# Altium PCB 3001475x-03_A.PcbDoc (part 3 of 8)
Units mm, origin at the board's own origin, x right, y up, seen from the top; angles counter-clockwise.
Board outline 100 x 72 mm, 12 copper layers (Top Layer, L2 GND, Layer 3, L4 GND, Layer 5, L6 PWR, L7 3V3, Layer 8, L9 GND, Layer 10, L11 GND, Bottom Layer), stack 1.735 mm thick; 428 components, 499 nets, 1973 pads, 1473 vias.
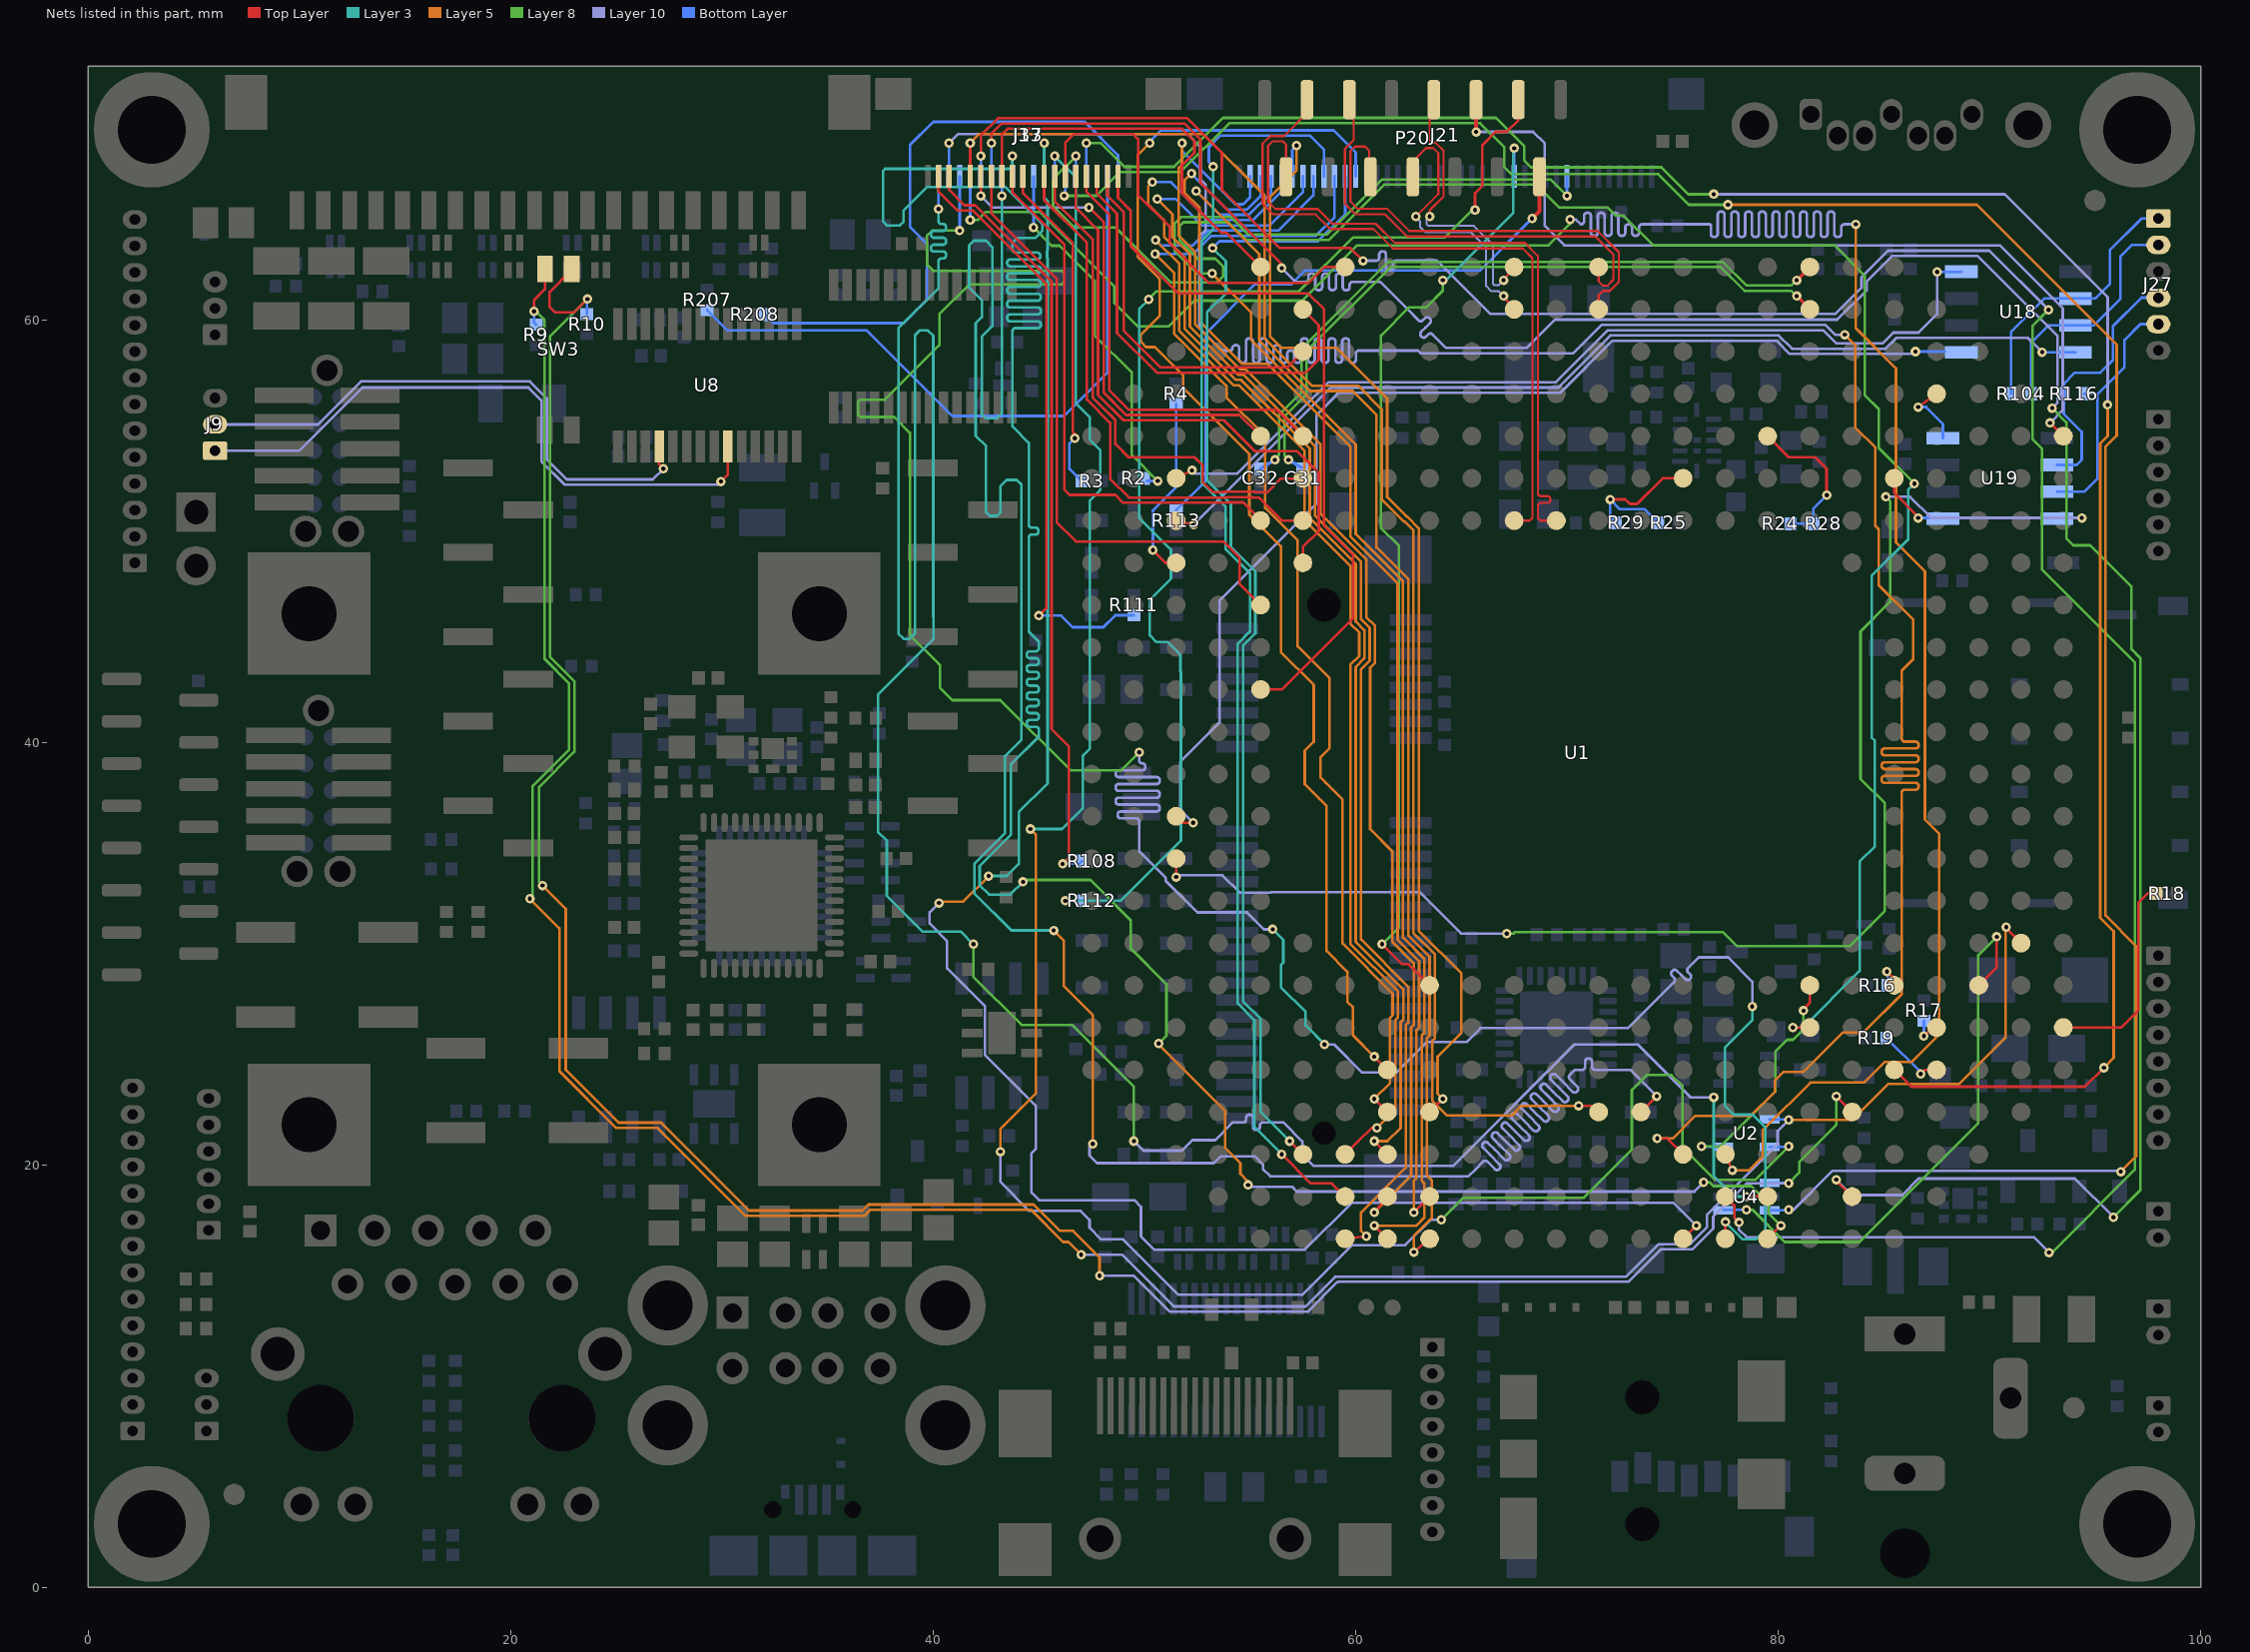
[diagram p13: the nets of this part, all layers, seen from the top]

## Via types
v1: diameter 0.45, hole 0.2, Top Layer to Bottom Layer, 1473 vias

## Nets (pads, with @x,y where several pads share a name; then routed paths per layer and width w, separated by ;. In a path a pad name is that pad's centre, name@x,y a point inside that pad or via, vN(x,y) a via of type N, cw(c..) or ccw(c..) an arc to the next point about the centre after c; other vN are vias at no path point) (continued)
BOOT_CFG_1_4: R18.1 U1.W24 | length 10
  Top Layer w0.125: U1.W24@93.5,26.5 96.25,26.5 97.05,27.3 97.05,32.4 97.5,32.85 R18.1@97.92,32.85
BOOT_CFG_1_5: R10.1 SW3.3 U1.AA19 U4.1 | length 117.3
  Top Layer w0.125: SW3.3@22.884,62.367 21.837,61.321 21.837,60.613 22.1,60.35 22.986,60.35 v1(23.625,60.988) ; SW3.3@22.885,62.367 SW3.3@22.885,62.41 ; v1(82.75,23.25) U1.AA19@83.5,22.5
  Layer 8 w0.125: v1(21.5,33.225) 21.337,33.388 21.337,37.884 23.013,39.559 23.013,42.891 21.85,44.054 21.85,58.854 21.85,59.214 v1(23.625,60.988) ; v1(80.5,19.125) 81,19.625 81,20.137 82.75,21.887 v1(82.75,23.25)
  Layer 5 w0.125: v1(21.5,33.225) 22.6,32.125 22.6,24.5 25.1,22 27.125,22 31.288,17.837 36.638,17.837 36.925,18.125 44.75,18.125 46,16.875 46.625,16.875 47.875,15.625 v1(47.875,14.75)
  Layer 10 w0.125: v1(47.875,14.75) 49.5,14.75 51.2,13.05 57.736,13.05 59.136,14.45 59.167,14.45 59.179,14.463 72.913,14.463 74.45,16 75.937,16 76.925,16.988 76.925,17.55 78.5,19.125 v1(80.5,19.125)
  Bottom Layer w0.125: R10.1@23.6,60.28 23.6,60.964 v1(23.625,60.988) ; U4.1@79.6,19.15 v1@80.475,19.15
BOOT_CFG_1_6: R9.1 SW3.4 U1.U23 U2.1 | length 127.4
  Top Layer w0.125: v1(21.1,60.4) 21.1,60.937 21.615,61.452 SW3.4@21.615,62.41 ; v1(90.8,31.25) 90.8,31.2 U1.U23@91.5,30.5
  Layer 8 w0.125: v1(20.9,32.6) 21.038,32.738 21.038,37.938 22.763,39.663 22.763,42.787 21.6,43.95 21.6,60 21.2,60.4 v1(21.1,60.4)
  Layer 5 w0.125: v1(20.9,32.6) 22.3,31.2 22.3,24.446 24.996,21.75 26.95,21.75 31.113,17.587 36.741,17.587 37.029,17.875 44.625,17.875 46.15,16.35 46.4,16.35 v1(47,15.75) ; v1(80.5,22.125) 83.5,22.125 85.212,23.837 88.571,23.837 90.763,26.029 90.763,31.213 v1(90.8,31.25)
  Layer 10 w0.125: v1(47,15.75) 48.946,15.75 51.396,13.3 57.632,13.3 59.032,14.7 59.063,14.7 59.076,14.713 72.809,14.713 74.346,16.25 75.833,16.25 76.625,17.042 76.625,17.625 79.975,20.975 79.975,21.608 80.492,22.125 v1(80.5,22.125)
  Bottom Layer w0.125: v1(21.1,60.4) 21.1,59.88 R9.1@21.2,59.78 ; U2.1@79.6,22.15 v1@80.475,22.15
BOOT_CFG_1_7: R19.1 U1.Y21 | length 3.2
  Top Layer w0.125: v1(86.75,24.3) 86.95,24.5 U1.Y21@87.5,24.5
  Bottom Layer w0.125: R19.1@85.13,26 86.75,24.38 v1(86.75,24.3)
BOOT_CFG_2_5: R16.1 U1.V20 | length 1.5
  Top Layer w0.125: v1(85.15,29.15) 85.5,28.8 U1.V20@85.5,28.5
  Bottom Layer w0.125: v1(85.15,29.15) 85.18,29.12 R16.1@85.18,28.5
BOOT_CFG_2_6: R17.1 U1.W21 | length 1.5
  Top Layer w0.125: v1(86.9,26.1) 87.3,26.5 U1.W21@87.5,26.5
  Bottom Layer w0.125: v1(86.9,26.1) R17.1@86.9,26.82
BOOT_MODE0: R24.1 R28.1 U1.E17 | length 7.7
  Top Layer w0.125: U1.E17@79.5,54.5 80.5,53.5 81.75,53.5 82.294,52.956 82.294,51.556 82.3,51.562 v1(82.3,51.7)
  Bottom Layer w0.125: R24.1@80.58,50.35 81.52,50.35 R28.1@81.67,50.5 ; R28.1@81.67,50.35 R28.1@81.67,50.5 ; v1(82.3,51.7) 81.67,51.07 R28.1@81.67,50.5
BOOT_MODE1: R25.1 R29.1 U1.F15 | length 8
  Top Layer w0.125: v1(72.05,51.5) 72.767,51.5 72.979,51.287 73.321,51.287 74.533,52.5 U1.F15@75.5,52.5
  Bottom Layer w0.125: R29.1@72.32,50.4 72.05,50.67 v1(72.05,51.5) 72.512,51.038 73.682,51.038 R25.1@74.32,50.4
BT_DISABLE_N: R4.2 U1.H3 | length 8.7
  Top Layer w0.125: v1(50.4,49.1) 51,48.5 U1.H3@51.5,48.5
  Bottom Layer w0.125: v1(50.4,49.1) 50.4,50.975 51.5,52.075 R4.2@51.5,56.02
CAN1_H: J27.2 R104.2 U18.7 | length 11.5
  Bottom Layer w0.125: R104.2@91.98,56.5 91.98,58.93 92.79,59.74 U18.7@94.075,59.74 94.95,59.74 96.2,60.99 96.2,63 96.75,63.55 J27.2@98,63.55
CAN1_L: J27.1 R104.1 U18.6 | length 13.1
  Bottom Layer w0.125: R104.1@91.02,56.5 91.02,59.42 92.61,61.01 U18.6@94.075,61.01 95.01,61.01 95.7,61.7 95.7,63.3 97.2,64.8 J27.1@98,64.8
CAN1_RXD: U1.F3 U18.4 | length 43
  Top Layer w0.125: U1.F3@51.5,52.5 v1(52.25,52.875)
  Layer 10 w0.125: v1(52.25,52.875) 52.413,52.712 54.384,52.712 58.721,57.05 69.483,57.05 71.946,59.513 82.137,59.513 82.763,58.887 84.937,58.887 85.45,59.4 86.65,59.4 87.525,60.275 v1(87.525,62.275)
  Bottom Layer w0.125: v1(87.525,62.275) 88.67,62.275 U18.4@88.675,62.28
CAN1_STBY: U1.G3 U18.8 | length 47.1
  Top Layer w0.125: U1.G3@51.5,50.5 v1(52.325,50.3)
  Layer 10 w0.125: v1(52.325,50.3) 58.825,56.8 69.587,56.8 72.049,59.263 80.029,59.263 80.654,58.637 85.087,58.637 85.6,59.15 91.825,59.15 v1(92.5,58.475)
  Bottom Layer w0.125: v1@92.5,58.47 U18.8@94.075,58.47
CAN1_TXD: U1.P3 U18.1 | length 54.7
  Top Layer w0.125: U1.P3@51.5,36.5 51.8,36.2 v1(52.3,36.2)
  Layer 10 w0.125: v1(52.3,36.2) 51.687,36.813 51.687,39.074 53.55,40.937 53.55,46.712 58.15,51.312 58.15,55.5 59.2,56.55 69.69,56.55 72.153,59.013 79.925,59.013 80.55,58.387 86.387,58.387 v1(86.5,58.5)
  Bottom Layer w0.125: v1(86.5,58.5) 87.895,58.5
CAN2_H: J27.5 R116.2 U19.7 | length 11.8
  Bottom Layer w0.125: U19.7@93.2,51.865 94.49,51.865 95.125,52.5 95.125,56.5 ; R116.2@94.48,56.5 95.125,56.5 ; J27.5@98,59.8 97.15,59.8 96.4,59.05 96.4,57.775 95.125,56.5
CAN2_L: J27.4 R116.1 U19.6 | length 12.3
  Bottom Layer w0.125: U19.6@93.2,53.135 94.135,53.135 94.375,53.375 94.375,54.7 93.52,55.555 R116.1@93.52,56.5 93.52,56.97 94.05,57.5 95.25,57.5 95.85,58.1 95.85,59.7 97.2,61.05 J27.4@98,61.05
CAN2_RXD: U1.D21 U19.4 | length 3.3
  Top Layer w0.125: v1(86.625,55.875) U1.D21@87.5,56.5
  Bottom Layer w0.125: v1(86.625,55.875) 87,55.875 87.8,55.075 U19.4@87.8,54.405
CAN2_STBY: U1.R3 U19.8 | length 68.2
  Top Layer w0.125: v1(51.5,33.625) U1.R3@51.5,34.5
  Layer 8 w0.125: v1(67.15,30.95) 67.467,30.95 67.529,31.013 77.387,31.013 78.05,30.35 83.375,30.35 85.05,32.025 85.05,37.125 83.9,38.275 83.9,45.25 85.3,46.65 85.3,51.425 v1(85.1,51.625)
  Layer 10 w0.125: v1(51.5,33.625) 51.588,33.713 53.687,33.713 54.513,32.887 55.971,32.887 55.996,32.913 63.021,32.913 64.983,30.95 v1(67.15,30.95) ; v1(85.1,51.625) 86.25,51.625 87.25,50.625 v1(94.375,50.625)
  Bottom Layer w0.125: U19.8@93.23,50.625 v1(94.375,50.625)
CAN2_TXD: U1.F20 U19.1 | length 3.5
  Top Layer w0.125: U1.F20@85.5,52.5 85.5,51.808 86.625,50.683 v1(86.625,50.625)
  Bottom Layer w0.125: v1(86.625,50.625) U19.1@87.77,50.625
CLK1_N: C31.1 U1.B18 | length 32.8
  Top Layer w0.157: v1(80.875,61.125) U1.B18@81.5,60.5
  Layer 8 w0.119: v1(56.825,53.375) 56.622,53.578 56.622,55.422 57.598,56.398 57.669,56.469 57.669,58.524 61.645,62.5 77.28,62.5 78.402,61.378 80.622,61.378 v1(80.875,61.125)
  Bottom Layer w0.157: v1(56.825,53.375) C31.1@57.5,52.96
CLK1_P: C32.1 U1.A18 | length 33.2
  Top Layer w0.157: v1(80.875,61.875) U1.A18@81.5,62.5
  Layer 8 w0.119: v1(56.175,53.375) 56.175,53.425 56.378,53.628 56.378,55.523 57.425,56.57 57.425,58.625 61.544,62.744 77.381,62.744 78.503,61.622 80.622,61.622 v1(80.875,61.875)
  Bottom Layer w0.157: C32.1@55.5,52.96 v1(56.175,53.375)
CONSOLE_RX: J9.2 U8.4 | length 27
  Top Layer w0.125: U8.4@27.025,54.005 27.025,53.155 v1(27.225,52.955)
  Layer 10 w0.125: J9.2@6,55.05 10.872,55.05 12.909,57.087 20.902,57.087 21.7,56.289 21.7,53.404 22.654,52.45 26.72,52.45 v1(27.225,52.955)
CONSOLE_TX: J9.1 U8.9 | length 30.6
  Top Layer w0.125: v1(29.95,52.35) 30.275,52.675 U8.9@30.275,54.005
  Layer 10 w0.125: J9.1@6,53.8 9.975,53.8 12.975,56.8 20.833,56.8 21.45,56.183 21.45,53.3 22.55,52.2 29.8,52.2 v1(29.95,52.35)
CSI0_DAT12: J17.2 U1.L5 | length 34.9
  Top Layer w0.125: J17.2@48.75,66.8 48.75,65.775 49.35,65.175 49.35,63.5 51.6,61.25 57.75,61.25 58.5,60.5 58.5,50.25 59.875,48.875 59.875,45.875 56.5,42.5 U1.L5@55.5,42.5
CSI0_DAT13: J17.3 U1.C6 | length 17.1
  Top Layer w0.125: J17.3@48.25,66.8 48.25,65.875 49.025,65.1 49.025,59.479 50.754,57.75 56.75,57.75 U1.C6@57.5,58.5
CSI0_DAT14: J17.4 U1.B6 | length 21.1
  Top Layer w0.125: J17.4@47.75,66.8 47.75,65.975 48.7,65.025 48.7,59.385 50.585,57.5 57.625,57.5 58.25,58.125 58.25,59.75 U1.B6@57.5,60.5
CSI0_DAT15: J17.5 U1.E6 | length 20.6
  Top Layer w0.125: J17.5@47.25,66.8 47.25,66.075 48.337,64.988 48.337,56.663 49.25,55.75 56.25,55.75 U1.E6@57.5,54.5
CSI0_DAT16: J17.6 U1.H6 | length 27.3
  Top Layer w0.125: J17.6@46.75,66.8 46.75,65.3 47.8,64.25 47.8,56.45 49,55.25 53.75,55.25 55.212,53.788 57.212,53.788 58.25,52.75 58.25,50 57.5,49.25 U1.H6@57.5,48.5
CSI0_DAT17: J17.7 U1.A7 | length 20.3
  Top Layer w0.125: J17.7@46.25,66.8 46.25,68.375 46.675,68.8 49.45,68.8 49.7,68.55 49.7,65.9 51.2,64.4 51.2,63.6 53.05,61.75 57.75,61.75 58.5,62.5 U1.A7@59.5,62.5
CSI0_DAT18: J17.8 U1.F6 | length 24.5
  Top Layer w0.125: J17.8@45.75,66.8 45.75,65.625 47.55,63.825 47.55,56.325 48.625,55.25 48.625,54.125 49.25,53.5 52.375,53.5 52.75,53.125 52.75,52.321 53.228,51.843 53.772,51.843 53.792,51.863 55.208,51.863 55.228,51.843 55.81,51.843 56.454,52.487 57.5,52.487 U1.F6@57.5,52.5
CSI0_DAT19: J17.9 U1.G6 | length 25.6
  Top Layer w0.125: J17.9@45.25,66.8 45.25,65.675 47.275,63.65 47.275,56.225 48.375,55.125 48.375,52.475 49.257,51.593 53.876,51.593 53.895,51.613 55.105,51.613 55.124,51.593 55.407,51.593 56.5,50.5 U1.G6@57.5,50.5
CSI0_GPIO: J17.15 U1.E5 | length 23.6
  Top Layer w0.125: v1(42.25,65.875) J17.15@42.25,66.8 ; v1(47.375,65.325) 48.075,64.625 48.075,56.55 49.125,55.5 54.5,55.5 U1.E5@55.5,54.5
  Layer 10 w0.125: v1(42.25,65.875) 42.8,65.325 v1(47.375,65.325)
CSI0_HSYNC: J17.13 U1.A5 | length 19.3
  Top Layer w0.125: J17.13@43.25,66.8 43.25,68.775 43.525,69.05 51.775,69.05 52.363,68.462 52.363,67.913 51.775,67.325 51.775,66 53.65,64.125 53.875,64.125 U1.A5@55.5,62.5
CSI0_I2C_SCL: J17.18 R108.2 | length 36.3
  Top Layer w0.125: J17.18@40.75,66.8 40.75,66.15 41.475,65.425 41.987,65.425 45.6,61.812 45.6,40.625 46.425,39.8 46.425,34.55 v1(46.125,34.25)
  Bottom Layer w0.125: v1(46.125,34.25) 46.895,34.25 R108.2@47.02,34.375
CSI0_I2C_SDA: J17.19 R111.2 | length 28.5
  Top Layer w0.125: J17.19@40.25,66.8 40.25,66.075 41.15,65.175 41.883,65.175 45.35,61.708 45.35,46.35 v1(45,46)
  Bottom Layer w0.125: v1(45,46) 46.05,46 46.6,45.45 48.05,45.45 48.62,46.02 R111.2@49.5,46.02
CSI0_MCLK: J17.11 R3.2 | length 15.8
  Top Layer w0.125: J17.11@44.25,66.8 44.25,66 46.6,63.65 46.6,54.7 46.7,54.6 v1(46.7,54.4)
  Bottom Layer w0.125: v1(46.7,54.4) 46.45,54.15 46.45,52.945 R3.2@47.02,52.375
CSI0_PIXCLK: J17.12 U1.G5 | length 25.8
  Top Layer w0.125: J17.12@43.75,66.8 43.75,66.025 46.213,63.562 46.213,51.962 46.462,51.713 48.621,51.713 48.99,51.343 53.979,51.343 53.999,51.363 54.671,51.363 55.5,50.533 U1.G5@55.5,50.5
CSI0_RESET_N: J17.16 U1.AA13 | length 72.9
  Top Layer w0.125: J17.16@41.75,66.8 v1(41.75,68.375) ; v1(70.55,22.8) 71.2,22.8 U1.AA13@71.5,22.5
  Layer 5 w0.125: v1(41.75,68.375) 42.175,68.8 52.775,68.8 55.687,65.888 55.687,59.126 57.927,56.886 60.114,56.886 61.237,55.763 61.237,51.507 62.302,50.442 62.329,50.442 62.737,50.034 62.737,30.968 63.75,29.956 63.75,26 63.625,25.875 63.625,23.042 64.329,22.337 67.387,22.337 67.85,22.8 v1(70.55,22.8)
CSI0_VSYNC: J17.14 U1.J5 | length 29.7
  Top Layer w0.125: J17.14@42.75,66.8 42.75,65.05 45.85,61.95 45.85,50.417 46.754,49.513 53.737,49.513 54.5,48.75 54.5,47.5 U1.J5@55.5,46.5
CSI1_DAT12: J33.2 U1.AC17 | length 128.7
  Top Layer w0.125: v1(78.5,18.5) U1.AC17@79.5,18.5
  Layer 8 w0.125: v1(41.9,30.45) 41.9,28.912 44.187,26.625 46.575,26.625 49.5,23.7 v1(49.5,21.125)
  Layer 10 w0.125: v1(49.5,21.125) 49.95,20.675 51.775,20.675 52.275,21.175 53.35,21.175 54.188,22.013 54.65,22.013 54.666,22.013 ccw(c54.666,22.159) 54.812,22.159 54.812,22.229 cw(c54.959,22.229) 54.959,22.375 54.991,22.375 cw(c54.991,22.229) 55.137,22.229 55.137,22.013 55.137,21.796 ccw(c55.284,21.796) 55.284,21.65 55.316,21.65 ccw(c55.316,21.796) 55.463,21.796 55.463,21.866 cw(c55.609,21.866) 55.609,22.013 56.571,22.013 57.475,21.108 57.475,20.5 58.025,19.95 64.6,19.95 70.35,25.7 73.35,25.7 75.85,23.2 v1(76.95,23.2)
  Layer 3 w0.125: v1(40.25,65.25) 40.25,64.684 ccw(c40.396,64.684) 40.396,64.538 40.462,64.538 cw(c40.462,64.391) 40.608,64.391 40.608,64.359 cw(c40.462,64.359) 40.462,64.213 40.038,64.213 ccw(c40.038,64.066) 39.892,64.066 39.892,64.034 ccw(c40.038,64.034) 40.038,63.887 40.462,63.887 cw(c40.462,63.741) 40.608,63.741 40.608,63.709 cw(c40.462,63.709) 40.462,63.562 40.038,63.562 ccw(c40.038,63.416) 39.892,63.416 39.892,63.384 ccw(c40.038,63.384) 40.038,63.237 40.462,63.237 cw(c40.462,63.091) 40.608,63.091 40.608,63.059 cw(c40.462,63.059) 40.462,62.912 40.396,62.912 ccw(c40.396,62.766) 40.25,62.766 40.25,61.5 38.35,59.6 38.35,45.15 38.6,44.9 38.869,44.9 39.138,45.169 39.138,59.287 39.35,59.5 39.75,59.5 40,59.25 40,45.946 40.013,45.933 40.013,44.896 37.387,42.271 37.387,35.763 37.8,35.35 37.8,32.742 39.492,31.05 41.3,31.05 v1(41.9,30.45) ; v1(76.95,23.2) 76.95,19.475 77.925,18.5 v1(78.5,18.5)
  Bottom Layer w0.125: v1(40.25,65.25) J33.2@40.25,66.8
CSI1_DAT13: J33.3 U1.AB15 | length 130.5
  Top Layer w0.125: v1(74.275,21.25) 74.75,21.25 U1.AB15@75.5,20.5
  Layer 5 w0.125: v1(74.275,21.25) 75,21.25 76.075,22.325 78.7,22.325 79.85,23.475 79.85,24 80.25,24.4 81.2,24.4 83.075,26.275 84.05,26.275 85.85,28.075 85.85,37.616 cw(c85.996,37.616) 85.996,37.762 86.503,37.762 ccw(c86.503,37.909) 86.649,37.909 86.649,37.941 ccw(c86.503,37.941) 86.503,38.087 85.047,38.087 cw(c85.047,38.234) 84.901,38.234 84.901,38.266 cw(c85.047,38.266) 85.047,38.412 86.503,38.412 ccw(c86.503,38.559) 86.649,38.559 86.649,38.591 ccw(c86.503,38.591) 86.503,38.737 85.047,38.737 cw(c85.047,38.884) 84.901,38.884 84.901,38.916 cw(c85.047,38.916) 85.047,39.062 86.503,39.062 ccw(c86.503,39.209) 86.649,39.209 86.649,39.241 ccw(c86.503,39.241) 86.503,39.388 85.047,39.388 cw(c85.047,39.534) 84.901,39.534 84.901,39.566 cw(c85.047,39.566) 85.047,39.713 86.503,39.713 ccw(c86.503,39.859) 86.649,39.859 86.649,39.891 ccw(c86.503,39.891) 86.503,40.038 85.996,40.038 cw(c85.996,40.184) 85.85,40.184 85.85,43.4 86.4,43.95 86.4,45.8 84.763,47.437 84.763,50.087 84.6,50.25 84.6,53.95 83.65,54.9 83.65,58.8 v1(83.15,59.3)
  Layer 10 w0.125: v1(40.75,68.375) 41.175,68.8 52.025,68.8 52.65,68.175 52.65,66.65 52.9,66.4 52.9,64.275 52.6,63.975 52.6,59.613 53.663,58.55 54,58.55 54.053,58.55 ccw(c54.053,58.659) 54.163,58.659 cw(c54.309,58.659) 54.309,58.806 54.341,58.806 cw(c54.341,58.659) 54.488,58.659 54.488,58.55 54.488,58.121 ccw(c54.634,58.121) 54.634,57.975 54.666,57.975 ccw(c54.666,58.121) 54.813,58.121 54.813,58.55 54.813,58.979 cw(c54.959,58.979) 54.959,59.125 54.991,59.125 cw(c54.991,58.979) 55.138,58.979 55.138,58.55 55.138,58.121 ccw(c55.284,58.121) 55.284,57.975 55.316,57.975 ccw(c55.316,58.121) 55.463,58.121 55.463,58.55 55.463,58.979 cw(c55.609,58.979) 55.609,59.125 55.641,59.125 cw(c55.641,58.979) 55.788,58.979 55.788,58.55 55.788,58.121 ccw(c55.934,58.121) 55.934,57.975 55.966,57.975 ccw(c55.966,58.121) 56.113,58.121 56.113,58.55 56.113,58.654 cw(c56.259,58.654) 56.259,58.8 56.291,58.8 cw(c56.291,58.654) 56.438,58.654 56.438,58.55 56.438,58.121 ccw(c56.584,58.121) 56.584,57.975 56.616,57.975 ccw(c56.616,58.121) 56.763,58.121 56.763,58.404 cw(c56.909,58.404) 56.909,58.55 56.941,58.55 cw(c56.941,58.404) 57.088,58.404 57.088,58.121 ccw(c57.234,58.121) 57.234,57.975 57.266,57.975 ccw(c57.266,58.121) 57.413,58.121 57.413,58.55 57.413,58.979 cw(c57.559,58.979) 57.559,59.125 57.591,59.125 cw(c57.591,58.979) 57.738,58.979 57.738,58.55 57.738,58.121 ccw(c57.884,58.121) 57.884,57.975 57.916,57.975 ccw(c57.916,58.121) 58.063,58.121 58.063,58.55 58.063,58.979 cw(c58.209,58.979) 58.209,59.125 58.241,59.125 cw(c58.241,58.979) 58.388,58.979 58.388,58.55 58.388,58.121 ccw(c58.534,58.121) 58.534,57.975 58.566,57.975 ccw(c58.566,58.121) 58.713,58.121 58.713,58.55 58.713,58.979 cw(c58.859,58.979) 58.859,59.125 58.891,59.125 cw(c58.891,58.979) 59.038,58.979 59.038,58.55 59.038,58.121 ccw(c59.184,58.121) 59.184,57.975 59.216,57.975 ccw(c59.216,58.121) 59.363,58.121 59.363,58.55 59.363,58.979 cw(c59.509,58.979) 59.509,59.125 59.541,59.125 cw(c59.541,58.979) 59.688,58.979 59.688,58.55 59.688,58.121 ccw(c59.834,58.121) 59.834,57.975 59.866,57.975 ccw(c59.866,58.121) 60.013,58.121 60.013,58.404 cw(c60.159,58.404) 60.159,58.55 60.35,58.55 62.95,58.55 63.075,58.425 70.3,58.425 71.638,59.763 82.241,59.763 82.704,59.3 v1(83.15,59.3)
  Bottom Layer w0.125: J33.3@40.75,66.8 v1(40.75,68.375)
CSI1_DAT14: J33.4 U1.AD16 | length 128.1
  Top Layer w0.125: U1.AD16@77.5,16.5 v1(77.5,17.3)
  Layer 8 w0.125: 40.25,43.725 40.325,43.65 ; v1(41.25,64.225) 39.95,64.225 39.7,63.975 39.7,62.625 40,62.325 46.075,62.325 46.2,62.2 46.2,61.8 46.075,61.675 41.692,61.675 40.287,60.271 40.287,58.804 37.708,56.225 36.55,56.225 36.45,56.125 36.45,55.5 36.55,55.4 38.15,55.4 38.9,54.65 38.9,45.075 40.325,43.65 ; v1(49.75,39.525) 48.908,38.683 46.492,38.683 43.175,42 40.9,42 40.325,42.575 40.325,43.65
  Layer 10 w0.125: v1(49.75,39.525) 49.75,39.168 49.75,39.152 ccw(c49.896,39.152) 49.896,39.006 cw(c49.896,38.859) 50.043,38.859 50.043,38.827 cw(c49.896,38.827) 49.896,38.681 49.75,38.681 48.783,38.681 ccw(c48.783,38.534) 48.637,38.534 48.637,38.502 ccw(c48.783,38.502) 48.783,38.356 49.75,38.356 50.579,38.356 cw(c50.579,38.209) 50.725,38.209 50.725,38.177 cw(c50.579,38.177) 50.579,38.031 49.75,38.031 48.783,38.031 ccw(c48.783,37.884) 48.637,37.884 48.637,37.852 ccw(c48.783,37.852) 48.783,37.706 49.75,37.706 50.579,37.706 cw(c50.579,37.559) 50.725,37.559 50.725,37.527 cw(c50.579,37.527) 50.579,37.381 49.75,37.381 48.783,37.381 ccw(c48.783,37.234) 48.637,37.234 48.637,37.202 ccw(c48.783,37.202) 48.783,37.056 49.75,37.056 50.579,37.056 cw(c50.579,36.909) 50.725,36.909 50.725,36.877 cw(c50.579,36.877) 50.579,36.731 49.75,36.731 48.873,36.731 ccw(c48.873,36.584) 48.727,36.584 48.727,36.552 ccw(c48.873,36.552) 48.873,36.406 49.604,36.406 cw(c49.604,36.259) 49.75,36.259 49.75,35.55 49.75,34.85 51,33.6 51,33.454 52.504,31.95 54.85,31.95 55.65,31.15 v1(56.075,31.15) ; v1(58.525,25.7) 58.975,25.7 60.3,24.375 61.925,24.375 63.363,25.813 65.238,25.813 65.9,26.475 72.892,26.475 74.258,27.842 75.072,28.655 ccw(c74.969,28.759) 75.072,28.862 74.974,28.96 cw(c75.078,29.063) 74.974,29.167 74.997,29.19 cw(c75.101,29.086) 75.204,29.19 75.405,28.989 75.606,28.788 ccw(c75.71,28.891) 75.813,28.788 75.836,28.811 ccw(c75.733,28.914) 75.836,29.017 75.739,29.115 cw(c75.842,29.218) 75.739,29.322 75.75,29.333 76.242,29.825 77.625,29.825 78.775,28.675 v1(78.775,27.5)
  Layer 3 w0.125: v1(56.075,31.15) 56.575,30.65 56.575,29.575 56.462,29.462 56.462,29.271 56.463,28.412 57.625,27.25 57.625,26.6 v1(58.525,25.7) ; v1(77.5,17.3) 78.325,16.475 78.925,16.475 79.4,16.95 79.4,21.775 78.8,22.375 77.9,22.375 77.475,22.8 77.475,25.55 78.775,26.85 v1(78.775,27.5)
  Bottom Layer w0.125: v1(41.25,64.225) J33.4@41.25,66.8
CSI1_DAT15: J33.5 U1.AB16 | length 130
  Top Layer w0.125: U1.AB16@77.5,20.5 v1(77.825,19.75)
  Layer 8 w0.125: v1(41.75,64.725) 42.1,64.725 42.488,65.113 45.037,65.113 48.575,61.575 48.575,60.8 49.675,59.7 51.15,59.7 52.363,60.913 57.459,60.913 60.071,63.524 69.124,63.524 70.15,64.55 v1(70.15,64.75)
  Layer 5 w0.125: v1(77.825,19.75) 78.625,19.75 79.275,20.4 79.275,21.65 79.425,21.8 79.429,21.8 81.529,23.9 84.075,23.9 85.05,24.875 86.325,24.875 87.625,26.175 87.625,35.675 86.95,36.35 86.95,48.1 85.575,49.475 85.575,57.7 83.675,59.6 v1(83.675,64.525)
  Layer 10 w0.125: v1(70.15,64.75) 70.425,64.75 70.65,64.525 70.666,64.525 ccw(c70.666,64.671) 70.812,64.671 70.812,64.924 cw(c70.959,64.924) 70.959,65.07 70.991,65.07 cw(c70.991,64.924) 71.138,64.924 71.138,64.525 71.138,64.126 ccw(c71.284,64.126) 71.284,63.98 71.316,63.98 ccw(c71.316,64.126) 71.463,64.126 71.463,64.525 71.463,64.924 cw(c71.609,64.924) 71.609,65.07 71.641,65.07 cw(c71.641,64.924) 71.788,64.924 71.788,64.525 71.788,64.126 ccw(c71.934,64.126) 71.934,63.98 71.966,63.98 ccw(c71.966,64.126) 72.113,64.126 72.113,64.525 72.113,64.924 cw(c72.259,64.924) 72.259,65.07 72.291,65.07 cw(c72.291,64.924) 72.438,64.924 72.438,64.525 72.438,64.126 ccw(c72.584,64.126) 72.584,63.98 72.616,63.98 ccw(c72.616,64.126) 72.763,64.126 72.763,64.379 cw(c72.909,64.379) 72.909,64.525 72.941,64.525 cw(c72.941,64.379) 73.088,64.379 73.088,64.126 ccw(c73.234,64.126) 73.234,63.98 73.266,63.98 ccw(c73.266,64.126) 73.413,64.126 73.413,64.379 cw(c73.559,64.379) 73.559,64.525 74.45,64.525 76.75,64.525 cw(c76.75,64.463) 76.812,64.463 76.812,64.071 ccw(c76.959,64.071) 76.959,63.925 76.991,63.925 ccw(c76.991,64.071) 77.137,64.071 77.137,64.525 77.137,64.979 cw(c77.284,64.979) 77.284,65.125 77.316,65.125 cw(c77.316,64.979) 77.462,64.979 77.462,64.525 77.462,64.071 ccw(c77.609,64.071) 77.609,63.925 77.641,63.925 ccw(c77.641,64.071) 77.787,64.071 77.787,64.525 77.787,64.979 cw(c77.934,64.979) 77.934,65.125 77.966,65.125 cw(c77.966,64.979) 78.112,64.979 78.112,64.525 78.112,64.071 ccw(c78.259,64.071) 78.259,63.925 78.291,63.925 ccw(c78.291,64.071) 78.437,64.071 78.437,64.525 78.437,64.979 cw(c78.584,64.979) 78.584,65.125 78.616,65.125 cw(c78.616,64.979) 78.762,64.979 78.762,64.525 78.762,64.071 ccw(c78.909,64.071) 78.909,63.925 78.941,63.925 ccw(c78.941,64.071) 79.087,64.071 79.087,64.525 79.087,64.979 cw(c79.234,64.979) 79.234,65.125 79.266,65.125 cw(c79.266,64.979) 79.412,64.979 79.412,64.525 79.412,64.071 ccw(c79.559,64.071) 79.559,63.925 79.591,63.925 ccw(c79.591,64.071) 79.737,64.071 79.737,64.525 79.737,64.979 cw(c79.884,64.979) 79.884,65.125 79.916,65.125 cw(c79.916,64.979) 80.062,64.979 80.062,64.525 80.062,64.071 ccw(c80.209,64.071) 80.209,63.925 80.241,63.925 ccw(c80.241,64.071) 80.387,64.071 80.387,64.525 80.387,64.979 cw(c80.534,64.979) 80.534,65.125 80.566,65.125 cw(c80.566,64.979) 80.712,64.979 80.712,64.525 80.712,64.071 ccw(c80.859,64.071) 80.859,63.925 80.891,63.925 ccw(c80.891,64.071) 81.037,64.071 81.037,64.525 81.037,64.979 cw(c81.184,64.979) 81.184,65.125 81.216,65.125 cw(c81.216,64.979) 81.362,64.979 81.362,64.525 81.362,64.071 ccw(c81.509,64.071) 81.509,63.925 81.541,63.925 ccw(c81.541,64.071) 81.687,64.071 81.687,64.525 81.687,64.979 cw(c81.834,64.979) 81.834,65.125 81.866,65.125 cw(c81.866,64.979) 82.012,64.979 82.012,64.525 82.012,64.071 ccw(c82.159,64.071) 82.159,63.925 82.191,63.925 ccw(c82.191,64.071) 82.337,64.071 82.337,64.525 82.337,64.979 cw(c82.484,64.979) 82.484,65.125 82.516,65.125 cw(c82.516,64.979) 82.662,64.979 82.662,64.525 82.662,64.071 ccw(c82.809,64.071) 82.809,63.925 82.841,63.925 ccw(c82.841,64.071) 82.987,64.071 82.987,64.379 cw(c83.134,64.379) 83.134,64.525 83.15,64.525 v1(83.675,64.525)
  Bottom Layer w0.125: v1(41.75,64.725) J33.5@41.75,66.8
CSI1_DAT16: J33.6 U1.AC16 | length 127.4
  Top Layer w0.125: v1(42.25,67.75) 42.25,68.725 43.075,69.55 52.025,69.55 53.663,67.912 53.663,66.154 56.417,63.4 59.75,63.4 v1(60.35,62.8) ; U1.AC16@77.5,18.5 77.925,18.075 77.925,17.5 v1(78.15,17.275)
  Layer 8 w0.125: v1(92.8,60.475) 92.05,59.725 92.05,54.35 92.5,53.9 92.5,48.175 96.89,43.785 96.89,19.769 92.971,15.85 v1(92.825,15.85)
  Layer 10 w0.125: v1(60.35,62.8) 60.95,62.8 60.966,62.8 ccw(c60.966,62.946) 61.112,62.946 61.112,63.095 cw(c61.259,63.095) 61.259,63.241 61.291,63.241 cw(c61.291,63.095) 61.437,63.095 61.437,62.8 61.437,62.505 ccw(c61.584,62.505) 61.584,62.359 61.616,62.359 ccw(c61.616,62.505) 61.763,62.505 61.763,62.654 cw(c61.909,62.654) 61.909,62.8 63.8,62.8 63.85,62.8 66.363,60.287 82.721,60.287 83.95,61.517 83.95,62.025 85.2,63.275 90,63.275 v1(92.8,60.475) ; v1(78.15,17.275) 78.15,16.925 78.5,16.575 92.1,16.575 v1(92.825,15.85)
  Bottom Layer w0.125: J33.6@42.25,66.8 v1(42.25,67.75)
CSI1_DAT17: J33.7 U1.AC19 | length 127.4
  Top Layer w0.125: v1(42.75,68.375) 42.75,68.8 43.25,69.3 51.9,69.3 52.65,68.55 52.65,66.483 56.5,62.633 v1(56.5,62.45) ; v1(82.75,19.3) 82.75,19.225 82.775,19.225 U1.AC19@83.5,18.5
  Layer 8 w0.125: v1(92.975,55.825) 93.65,55.15 93.65,49.65 93.975,49.325 94.775,49.325 96.725,47.375 96.725,44.4 97.15,43.975 97.15,18.8 v1(95.875,17.525)
  Layer 10 w0.125: v1(56.5,62.45) 57.15,61.8 57.6,61.8 57.616,61.8 ccw(c57.616,61.946) 57.762,61.946 57.762,62.048 cw(c57.909,62.048) 57.909,62.194 57.941,62.194 cw(c57.941,62.048) 58.087,62.048 58.087,61.8 58.087,61.552 ccw(c58.234,61.552) 58.234,61.406 58.266,61.406 ccw(c58.266,61.552) 58.412,61.552 58.412,61.8 58.412,62.048 cw(c58.559,62.048) 58.559,62.194 58.591,62.194 cw(c58.591,62.048) 58.737,62.048 58.737,61.8 58.737,61.552 ccw(c58.884,61.552) 58.884,61.406 58.916,61.406 ccw(c58.916,61.552) 59.063,61.552 59.063,61.8 59.063,62.048 cw(c59.209,62.048) 59.209,62.194 59.241,62.194 cw(c59.241,62.048) 59.388,62.048 59.388,61.8 59.388,61.552 ccw(c59.534,61.552) 59.534,61.406 59.566,61.406 ccw(c59.566,61.552) 59.713,61.552 59.713,61.654 cw(c59.859,61.654) 59.859,61.8 61.15,61.8 62.45,60.5 62.972,59.978 ccw(c63.075,60.081) 63.179,59.978 63.284,60.083 cw(c63.387,59.98) 63.491,60.083 63.514,60.06 cw(c63.41,59.957) 63.514,59.853 63.305,59.645 63.097,59.436 ccw(c63.2,59.333) 63.097,59.229 63.12,59.206 ccw(c63.223,59.31) 63.327,59.206 63.432,59.311 cw(c63.535,59.208) 63.639,59.311 63.65,59.3 64.275,58.675 64.625,58.675 68.092,58.675 69.429,60.013 82.799,60.013 84.2,61.413 84.2,61.825 85.4,63.025 89.45,63.025 93.225,59.25 93.225,56.075 v1(92.975,55.825) ; v1(82.75,19.3) 83.475,18.575 85.875,18.575 86.65,19.35 94.05,19.35 v1(95.875,17.525)
  Bottom Layer w0.125: J33.7@42.75,66.8 v1(42.75,68.375)
CSI1_DAT18: J33.8 U1.AA14 | length 128.5
  Top Layer w0.125: U1.AA14@73.5,22.5 v1(74.25,23.25)
  Layer 5 w0.125: v1(45.7,31.1) 46.175,30.625 46.175,28.475 47.55,27.1 v1(47.55,21)
  Layer 10 w0.125: v1(47.55,21) 47.4,20.85 47.4,20.45 47.763,20.087 48.204,20.087 53.284,20.087 53.609,20.413 55.224,20.413 55.613,20.024 55.613,19.804 55.954,19.462 65.337,19.462 65.663,19.787 66.025,20.15 cw(c66.128,20.046) 66.232,20.15 66.587,19.794 ccw(c66.691,19.898) 66.794,19.794 66.817,19.817 ccw(c66.714,19.921) 66.817,20.024 66.358,20.483 66.029,20.812 cw(c66.133,20.916) 66.029,21.019 66.052,21.042 cw(c66.155,20.939) 66.259,21.042 66.588,20.713 67.047,20.254 ccw(c67.15,20.357) 67.254,20.254 67.277,20.277 ccw(c67.173,20.38) 67.277,20.484 66.818,20.943 66.489,21.272 cw(c66.592,21.375) 66.489,21.479 66.512,21.502 cw(c66.615,21.398) 66.719,21.502 67.048,21.173 67.507,20.714 ccw(c67.61,20.817) 67.713,20.714 67.736,20.737 ccw(c67.633,20.84) 67.736,20.943 67.277,21.402 66.948,21.731 cw(c67.052,21.835) 66.948,21.938 66.971,21.961 cw(c67.075,21.858) 67.178,21.961 67.507,21.632 67.966,21.173 ccw(c68.07,21.277) 68.173,21.173 68.196,21.196 ccw(c68.093,21.3) 68.196,21.403 67.737,21.862 67.408,22.191 cw(c67.511,22.294) 67.408,22.398 67.431,22.421 cw(c67.534,22.317) 67.638,22.421 67.967,22.092 68.426,21.633 ccw(c68.529,21.736) 68.633,21.633 68.656,21.656 ccw(c68.552,21.759) 68.656,21.863 68.197,22.322 67.868,22.651 cw(c67.971,22.754) 67.868,22.857 67.891,22.88 cw(c67.994,22.777) 68.097,22.88 68.426,22.551 68.885,22.092 ccw(c68.989,22.196) 69.092,22.092 69.115,22.115 ccw(c69.012,22.219) 69.115,22.322 68.656,22.781 68.327,23.11 cw(c68.431,23.214) 68.327,23.317 68.35,23.34 cw(c68.454,23.237) 68.557,23.34 68.886,23.011 69.345,22.552 ccw(c69.448,22.655) 69.552,22.552 69.575,22.575 ccw(c69.471,22.678) 69.575,22.782 69.116,23.241 68.787,23.57 cw(c68.89,23.673) 68.787,23.777 68.81,23.8 cw(c68.913,23.696) 69.017,23.8 69.346,23.471 69.805,23.012 ccw(c69.908,23.115) 70.011,23.012 70.034,23.035 ccw(c69.931,23.138) 70.034,23.242 69.575,23.7 69.246,24.03 cw(c69.35,24.133) 69.246,24.236 69.269,24.259 cw(c69.373,24.156) 69.476,24.259 69.805,23.93 70.264,23.471 ccw(c70.368,23.575) 70.471,23.471 70.494,23.494 ccw(c70.391,23.598) 70.494,23.701 70.139,24.057 cw(c70.242,24.16) 70.139,24.264 70.15,24.275 70.375,24.5 70.7,24.5 70.716,24.5 ccw(c70.716,24.646) 70.862,24.646 70.862,24.892 cw(c71.009,24.892) 71.009,25.038 71.041,25.038 cw(c71.041,24.892) 71.188,24.892 71.188,24.646 ccw(c71.334,24.646) 71.334,24.5 72.45,24.5 73,24.5 v1(74.25,23.25)
  Layer 3 w0.125: v1(43.25,65.875) 43.25,55.575 43.025,55.35 42.475,55.35 42.3,55.525 42.3,59.2 42.8,59.7 42.8,63.45 42.5,63.75 41.925,63.75 41.7,63.525 41.7,61.525 42.3,60.925 42.3,60.125 42.012,59.837 42.012,54.513 42.5,54.025 42.5,50.9 42.675,50.725 43.025,50.725 43.175,50.875 43.175,52.125 43.475,52.425 43.95,52.425 44.175,52.2 44.175,40.125 43.4,39.35 43.4,35.7 41.95,34.25 41.95,32.85 43.7,31.1 v1(45.7,31.1)
  Bottom Layer w0.125: v1(43.25,65.875) J33.8@43.25,66.8
CSI1_DAT19: J33.9 U1.AD17 | length 127.7
  Top Layer w0.125: U1.AD17@79.5,16.5 v1(80.125,17.125)
  Layer 8 w0.125: v1(44.25,33.4) 44.338,33.488 47.446,33.488 49.35,31.583 49.35,30.243 51.038,28.555 51.038,26.113 v1(50.675,25.75) ; v1(76.475,19.175) 76.75,19.175 76.925,19 78.725,19 79.55,18.175 79.55,17.7 v1(80.125,17.125)
  Layer 5 w0.125: v1(50.675,25.75) 50.675,25.692 53.821,22.545 53.821,20.8 54.537,20.084 54.537,19.579 54.9,19.217 v1(54.9,19.05)
  Layer 10 w0.125: v1(54.9,19.05) 54.988,18.962 56.996,18.962 57.221,18.737 76.037,18.737 v1(76.475,19.175)
  Layer 3 w0.125: v1(43.75,67.75) 43.75,67.275 43.625,67.15 37.725,67.15 37.625,67.05 37.625,64.65 37.8,64.475 38.425,64.475 38.6,64.65 38.6,65.183 39.704,66.288 43.421,66.288 45.163,64.546 45.163,64.204 44.833,63.875 43.975,63.875 43.75,63.65 43.75,63.334 ccw(c43.896,63.334) 43.896,63.188 44.92,63.188 cw(c44.92,63.041) 45.067,63.041 45.067,63.009 cw(c44.92,63.009) 44.92,62.863 43.646,62.863 ccw(c43.646,62.716) 43.5,62.716 43.5,62.684 ccw(c43.646,62.684) 43.646,62.538 44.945,62.538 cw(c44.945,62.391) 45.092,62.391 45.092,62.359 cw(c44.945,62.359) 44.945,62.212 43.646,62.212 ccw(c43.646,62.066) 43.5,62.066 43.5,62.034 ccw(c43.646,62.034) 43.646,61.887 44.945,61.887 cw(c44.945,61.741) 45.092,61.741 45.092,61.709 cw(c44.945,61.709) 44.945,61.562 43.646,61.562 ccw(c43.646,61.416) 43.5,61.416 43.5,61.384 ccw(c43.646,61.384) 43.646,61.237 44.945,61.237 cw(c44.945,61.091) 45.092,61.091 45.092,61.059 cw(c44.945,61.059) 44.945,60.912 43.646,60.912 ccw(c43.646,60.766) 43.5,60.766 43.5,60.734 ccw(c43.646,60.734) 43.646,60.587 44.945,60.587 cw(c44.945,60.441) 45.092,60.441 45.092,60.409 cw(c44.945,60.409) 44.945,60.262 43.646,60.262 ccw(c43.646,60.116) 43.5,60.116 43.5,60.084 ccw(c43.646,60.084) 43.646,59.937 44.945,59.937 cw(c44.945,59.791) 45.092,59.791 45.092,59.759 cw(c44.945,59.759) 44.945,59.612 43.896,59.612 ccw(c43.896,59.466) 43.75,59.466 43.75,54.95 44.525,54.175 44.525,50.309 ccw(c44.671,50.309) 44.671,50.163 44.835,50.163 cw(c44.835,50.016) 44.982,50.016 44.982,49.984 cw(c44.835,49.984) 44.835,49.838 44.671,49.838 ccw(c44.671,49.691) 44.525,49.691 44.525,45.25 45,44.775 45,44.459 cw(c44.854,44.459) 44.854,44.313 44.571,44.313 ccw(c44.571,44.166) 44.425,44.166 44.425,44.134 ccw(c44.571,44.134) 44.571,43.988 44.854,43.988 cw(c44.854,43.841) 45,43.841 45,43.809 cw(c44.854,43.809) 44.854,43.663 44.571,43.663 ccw(c44.571,43.516) 44.425,43.516 44.425,43.484 ccw(c44.571,43.484) 44.571,43.338 44.854,43.338 cw(c44.854,43.191) 45,43.191 45,43.159 cw(c44.854,43.159) 44.854,43.013 44.571,43.013 ccw(c44.571,42.866) 44.425,42.866 44.425,42.834 ccw(c44.571,42.834) 44.571,42.688 44.854,42.688 cw(c44.854,42.541) 45,42.541 45,42.509 cw(c44.854,42.509) 44.854,42.363 44.571,42.363 ccw(c44.571,42.216) 44.425,42.216 44.425,42.184 ccw(c44.571,42.184) 44.571,42.038 44.854,42.038 cw(c44.854,41.891) 45,41.891 45,41.859 cw(c44.854,41.859) 44.854,41.712 44.571,41.712 ccw(c44.571,41.566) 44.425,41.566 44.425,41.534 ccw(c44.571,41.534) 44.571,41.387 44.854,41.387 cw(c44.854,41.241) 45,41.241 45,41.209 cw(c44.854,41.209) 44.854,41.062 44.571,41.062 ccw(c44.571,40.916) 44.425,40.916 44.425,40.884 ccw(c44.571,40.884) 44.571,40.737 44.854,40.737 cw(c44.854,40.591) 45,40.591 45,40.275 43.675,38.95 43.675,35.621 42.2,34.146 42.2,33.238 42.638,32.8 43.65,32.8 v1(44.25,33.4)
  Bottom Layer w0.125: J33.9@43.75,66.8 v1(43.75,67.75)
CSI1_GPIO: J33.15 U1.W18 | length 93.1
  Top Layer w0.125: v1@80.65,26.475 80.675,26.5 v1(80.7,26.5) U1.W18@81.5,26.5
  Layer 8 w0.125: v1(46.75,67.75) 45.675,66.675 45.675,65.375 46.675,64.375 48.625,64.375 51.225,61.775 53.425,61.775 53.725,62.075 53.725,62.525 53.35,62.9 52.525,62.9 51.675,63.75 51.675,64.446 51.854,64.625 53.979,64.625 54.816,63.787 58.737,63.787 61.35,66.4 68.55,66.4 69.625,65.325 71.925,65.325 72.312,64.938 72.679,64.938 74.092,63.524 82.679,63.524 84.1,62.104 84.1,56.433 84.763,55.771 84.763,53.937 v1(86.45,52.25)
  Layer 3 w0.125: v1(80.7,26.5) 81.183,26.5 83.863,29.179 83.863,34.367 84.575,35.079 84.575,40.075 84.425,40.225 84.425,47.875 86.15,49.6 86.15,51.95 v1(86.45,52.25)
  Bottom Layer w0.125: J33.15@46.75,66.8 v1(46.75,67.75)
CSI1_HSYNC: J33.13 U2.3 | length 104.4
  Layer 8 w0.125: v1(64.05,17.4) 65.1,18.45 70.8,18.45 73.075,20.725 73.075,23.546 73.779,24.25 74.95,24.25 75.475,23.725 75.475,20.825 77,19.3 78.925,19.3 v1(80.5,20.875)
  Layer 5 w0.125: v1(43.175,20.625) 43.175,21.7 44.85,23.375 44.85,35.65 v1(44.6,35.9)
  Layer 10 w0.125: v1(43.175,20.625) 43.175,19.2 44.55,17.825 46.975,17.825 47.4,17.4 47.4,17.025 47.95,16.475 48.992,16.475 51.617,13.85 57.475,13.85 59.825,16.2 62.35,16.2 63.55,17.4 v1(64.05,17.4)
  Layer 3 w0.125: v1(44.6,35.9) 46.1,35.9 47.087,36.887 47.087,39.371 47.413,39.696 47.413,51.45 47.913,51.95 47.913,53.826 47.413,54.326 47.413,55.387 46.75,56.05 46.75,66.75 v1(45.75,67.75)
  Bottom Layer w0.125: J33.13@45.75,66.8 v1(45.75,67.75) ; U2.3@79.6,20.85 v1@80.475,20.85
CSI1_HSYNC/BTCFG2_3: U1.V18 U2.4 | length 11.4
  Top Layer w0.125: v1(81.2,27.3) 81.2,27.375 81.5,27.675 U1.V18@81.5,28.5
  Layer 8 w0.125: v1(76.375,20.875) 77.25,20.875 79.875,23.5 79.875,25.375 80.425,25.925 80.708,25.925 81.2,26.417 v1(81.2,27.3)
  Bottom Layer w0.125: v1@76.4,20.85 U2.4@77.4,20.85
CSI1_I2C_SCL: J33.18 R207.2 | length 31.2
  Bottom Layer w0.125: R207.2@29.3,60.47 30.27,59.5 36.85,59.5 40.9,55.45 46.2,55.45 48.25,57.5 J33.18@48.25,66.8
CSI1_I2C_SDA: J33.19 R208.2 | length 27.9
  Bottom Layer w0.125: R208.2@32.03,60.25 32.43,59.85 38.6,59.85 39.7,60.95 39.7,63.6 38.9,64.4 38.9,68.275 40,69.375 47.175,69.375 48.75,67.8 J33.19@48.75,66.8
CSI1_MCLK: J33.11 R2.2 | length 17.6
  Layer 8 w0.125: v1(44.75,64.375) 45.612,63.513 45.971,63.513 47.633,61.85 47.633,59.267 49.4,57.5 49.4,53.6 v1(50.625,52.375)
  Bottom Layer w0.125: v1(44.75,64.375) J33.11@44.75,66.8 ; R2.2@50.105,52.375 v1(50.625,52.375)
CSI1_PIXCLK: J33.12 U1.AD15 | length 92.6
  Top Layer w0.125: U1.AD15@75.5,16.5 v1(76.125,17.125)
  Layer 5 w0.125: v1(40.275,32.4) 40.338,32.463 41.428,32.463 42.619,33.653 v1(42.619,33.677)
  Layer 10 w0.125: v1(40.275,32.4) 39.825,31.95 39.825,31.425 40.658,30.592 40.658,29.305 42.45,27.514 42.45,25.2 44.86,22.789 44.86,20.76 44.65,20.55 44.65,18.689 45.014,18.325 49.525,18.325 49.837,18.013 49.837,16.613 50.461,15.99 57.59,15.99 59.8,18.2 75.05,18.2 v1(76.125,17.125)
  Layer 3 w0.125: v1(42.619,33.677) 42.621,33.675 43.483,33.675 44.05,34.242 44.05,36.7 45.413,38.063 45.413,62.904 45.387,62.929 45.387,63.271 45.413,63.296 45.413,65.637 45.25,65.8 v1(45.25,68.375)
  Bottom Layer w0.125: J33.12@45.25,66.8 v1(45.25,68.375)
CSI1_RESET_N: J33.16 U1.Y20 | length 103
  Top Layer w0.125: U1.Y20@85.5,24.5 86.3,23.7 94.525,23.7 v1(95.425,24.6)
  Layer 8 w0.125: v1(47.25,68.375) 47.925,68.375 49.05,67.25 51.4,67.25 53.713,69.563 66.646,69.563 67.975,68.233 67.975,67.55 68.3,67.225 74.475,67.225 75.75,65.95 v1(76.95,65.95)
  Layer 5 w0.125: v1(95.425,24.6) 95.887,25.062 95.887,31.059 95.25,31.696 95.25,54.15 95.6,54.5 v1(95.6,55.975)
  Layer 10 w0.125: v1(76.95,65.95) 90.725,65.95 95.6,61.075 v1(95.6,55.975)
  Bottom Layer w0.125: J33.16@47.25,66.8 v1(47.25,68.375)
CSI1_VSYNC: J33.14 U4.3 | length 114.7
  Layer 8 w0.125: v1(46.2,65.875) 47.725,65.875 48.85,67 51.7,67 54.013,69.313 65.896,69.313 67.025,68.183 67.025,67.25 67.375,66.9 74.325,66.9 75.775,65.45 v1(77.625,65.45)
  Layer 5 w0.125: v1(77.625,65.45) 89.4,65.45 96.025,58.825 96.025,54.525 95.5,54 95.5,31.8 96.95,30.35 96.95,20.413 v1(96.219,19.681)
  Layer 10 w0.125: v1(80.5,17.875) 80.725,17.875 82.563,19.713 96.187,19.713 v1(96.219,19.681)
  Bottom Layer w0.125: v1@46.25,65.875 J33.14@46.25,66.8 ; U4.3@79.6,17.85 v1@80.475,17.85
CSI1_VSYNC/BTCFG2_4: U1.V22 U4.4 | length 26.9
  Top Layer w0.125: U1.V22@89.5,28.5 90.35,29.35 v1(90.35,30.8)
  Layer 8 w0.125: v1(78.5,17.875) 78.792,17.875 80.317,16.35 83.85,16.35 89.475,21.975 89.475,29.925 v1(90.35,30.8)
  Bottom Layer w0.125: U4.4@77.425,17.875 v1(78.5,17.875)
CSI_CLK0_N: P20.8 U1.B11 | length 13.5
  Top Layer w0.104: P20.8@62.7,66.775 62.7,67.506 63.33,68.136 63.67,68.136 63.911,67.895 63.911,65.961 v1(62.85,64.9) ; v1(67,61.125) U1.B11@67.5,60.5
  Layer 10 w0.093: v1(62.85,64.9) 62.85,64.854 63.05,64.654 63.05,64.4 63.3,64.15 65.45,64.15 66.175,63.425 66.175,61.601 66.426,61.35 66.5,61.35 66.775,61.35 v1(67,61.125)
CSI_CLK0_P: P20.7 U1.A11 | length 13.5
  Top Layer w0.104: v1(63.5,64.9) 63.5,65.189 64.166,65.855 64.166,68.001 63.776,68.391 63.6,68.391 63.5,68.491 63.5,70.225 P20.7@63.7,70.425 ; v1(67,61.875) U1.A11@67.5,62.5
  Layer 10 w0.093: v1(63.5,64.9) 63.35,64.75 63.35,64.55 63.45,64.45 65.6,64.45 66.5,63.55 66.5,61.7 66.55,61.65 66.775,61.65 v1(67,61.875)
CSI_D0_N: P20.14 U1.G12 | length 33.3
  Top Layer w0.104: P20.14@56.7,66.775 56.7,68.3 56.55,68.45 56.061,68.45 55.85,68.239 55.85,65.6 56.2,65.25 58.205,65.25 58.9,64.555 60.945,64.555 61.861,63.639 68.011,63.639 68.621,63.029 68.621,52 68.621,51.977 68.621,51.8 ccw(c68.766,51.8) 68.766,51.655 69.076,51.655 cw(c69.076,51.51) 69.221,51.51 69.221,51.478 cw(c69.076,51.478) 69.076,51.333 68.766,51.333 ccw(c68.766,51.188) 68.621,51.188 68.621,51.011 68.621,50.85 68.621,50.629 68.75,50.5 U1.G12@69.5,50.5
CSI_D0_P: P20.13 U1.G11 | length 33.2
  Top Layer w0.104: P20.13@57.7,70.425 57.639,70.364 57.639,69.739 56.605,68.705 55.955,68.705 55.595,68.345 55.595,65.494 56.094,64.995 58.099,64.995 58.794,64.3 60.839,64.3 61.755,63.384 67.905,63.384 68.366,62.923 68.366,50.629 68.237,50.5 U1.G11@67.5,50.5
CSI_D1_N: P20.11 U1.A13 | length 21.6
  Top Layer w0.104: P20.11@59.7,70.425 59.9,70.225 59.9,68.5 59.495,68.095 59.495,65.494 59.989,65 61.389,65 62.439,63.95 71.35,63.95 72.2,63.1 72.2,61.9 71.928,61.628 71.7,61.628 71.5,61.827 U1.A13@71.5,62.5
CSI_D1_P: P20.10 U1.B13 | length 21.7
  Top Layer w0.104: P20.10@60.7,66.775 60.639,66.836 60.639,68.011 60.45,68.2 59.961,68.2 59.75,67.989 59.75,65.6 60.095,65.255 61.495,65.255 62.545,64.205 71.456,64.205 72.455,63.206 72.455,61.794 72.033,61.373 71.7,61.373 71.5,61.173 U1.B13@71.5,60.5
CSI_I2C_SCL: P20.3 R112.2 | length 58.8
  Top Layer w0.125: v1(65.65,65.2) 65.65,66 66,66.35 66,68.275 66.625,68.9 67.15,68.9 67.7,69.45 P20.3@67.7,70.425
  Layer 8 w0.125: v1(50.2,60.975) 50.575,61.35 57.317,61.35 59.867,63.9 64.2,63.9 65.5,65.2 v1(65.65,65.2)
  Layer 3 w0.125: v1(46.25,32.5) 48.875,32.5 51.725,35.35 51.725,43.329 51.7,43.354 51.7,44.15 51.1,44.75 50.575,44.75 50.25,45.075 50.25,46.75 51.25,47.75 51.25,49.125 49.75,50.625 49.75,60.5 v1@50.225,60.975
  Bottom Layer w0.125: v1(46.25,32.5) R112.2@47.02,32.5
CSI_I2C_SDA: P20.2 R113.2 | length 28.8
  Top Layer w0.2: v1(68.35,64.8) 68.7,65.15 P20.2@68.7,66.775
  Bottom Layer w0.125: R113.2@51.5,50.98 52.9,52.38 52.9,59.358 55.225,61.683 56.95,61.683 57.617,62.35 65.9,62.35 v1(68.35,64.8)
CSI_RESET_N: P20.5 U1.E24 | length 41.6
  Top Layer w0.125: v1(92.875,55.125) U1.E24@93.5,54.5
  Top Layer w0.2: v1(65.7,68.9) P20.5@65.7,70.425
  Layer 10 w0.125: v1(65.7,68.9) 68.4,68.9 68.95,68.35 68.95,64.45 69.875,63.525 90.5,63.525 93.475,60.55 93.475,55.725 v1(92.875,55.125)
DISP0_CLK: J21.27 U1.V9 | length 45.9
  Top Layer w0.125: v1(61.25,30.45) 62.2,29.5 62.5,29.5 U1.V9@63.5,28.5
  Layer 8 w0.125: v1(61.25,30.45) 62.05,31.25 62.05,49.293 61.2,50.143 61.2,59.265 62.535,60.6 63.35,60.6 64.125,61.375 v1(64.125,61.875)
  Layer 3 w0.125: v1(64.125,61.875) 64.271,61.875 67.45,65.054 67.45,68.075 v1(67.5,68.125)
  Bottom Layer w0.125: J21.27@67.5,66.8 v1(67.5,68.125)
DISP0_CONTRAST: J21.32 U1.AD8 | length 77.3
  Top Layer w0.125: v1(60.875,17.125) U1.AD8@61.5,16.5
  Layer 8 w0.125: v1(53.2,62.2) 52.5,62.2 51.425,63.275 51.425,64.55 51.75,64.875 54.082,64.875 54.92,64.037 58.632,64.037 61.245,66.65 69.225,66.65 v1(70,65.875)
  Layer 5 w0.125: v1(53.2,62.2) 55.05,60.35 55.05,59.054 60,54.104 60,49.868 62.237,47.63 62.237,30.761 63.25,29.749 63.25,26.25 63.125,26.125 63.125,19.25 63.25,19.125 63.25,17.5 62.875,17.125 v1(60.875,17.125)
  Bottom Layer w0.125: v1(70,65.875) J21.32@70,66.8
DISP0_DAT0: J21.2 U1.AC8 | length 63.2
  Top Layer w0.125: v1(60.875,17.75) U1.AC8@61.5,18.5
  Layer 5 w0.125: v1(51.775,68.375) 51.775,67.35 51.625,67.2 51.625,63.979 52.4,63.204 52.4,59.788 54.526,57.663 54.782,57.663 58.325,54.119 58.325,50.836 60.5,48.661 60.5,45.933 60.913,45.52 60.913,43.768 60.687,43.543 60.687,35.896 61.737,34.846 61.737,30.554 62.75,29.542 62.75,26.625 62.625,26.5 62.625,19.5 v1(60.875,17.75)
  Bottom Layer w0.125: v1(51.775,68.375) 51.775,68 54.3,65.475 54.675,65.475 55,65.8 J21.2@55,66.8
DISP0_DAT1: J21.3 U1.AC9 | length 61
  Top Layer w0.125: v1(62.75,17.75) U1.AC9@63.5,18.5
  Layer 5 w0.125: v1(52.225,66.925) 51.9,66.6 51.9,66.025 52.6,65.325 52.6,63.357 52.65,63.307 52.65,59.892 54.617,57.925 55.825,57.925 59.75,54 59.75,49.764 61.987,47.527 61.987,30.658 63,29.645 63,26.5 62.875,26.375 62.875,19.375 62.75,19.25 v1(62.75,17.75)
  Bottom Layer w0.125: v1(52.225,66.925) 53.925,65.225 54.846,65.225 55.5,65.879 J21.3@55.5,66.8
DISP0_DAT2: J21.4 U1.AD9 | length 62.7
  Top Layer w0.125: v1(62.75,15.875) U1.AD9@63.5,16.5
  Layer 5 w0.125: v1(52.45,66.1) 55.437,63.113 55.437,59.022 57.824,56.636 59.848,56.636 60.987,55.496 60.987,49.234 62.487,47.734 62.487,30.865 63.5,29.852 63.5,29.146 63.5,26.125 63.375,26 63.375,19.5 63.6,19.275 63.6,17.475 62.75,16.625 v1(62.75,15.875)
  Bottom Layer w0.125: v1(52.45,66.1) 53.575,64.975 54.95,64.975 56,66.025 J21.4@56,66.8
DISP0_DAT3: J21.5 U1.AB8 | length 60.9
  Top Layer w0.125: v1(60.875,21.125) U1.AB8@61.5,20.5
  Layer 5 w0.125: v1(50.375,66.525) 50.175,66.325 50.175,65.475 50.931,64.719 50.931,63.944 51.9,62.975 51.9,59.581 54.318,57.163 54.574,57.163 57.825,53.912 57.825,50.629 60,48.454 60,45.979 60,45.726 60.413,45.313 60.413,43.976 60,43.563 60,30.563 62.25,28.313 62.25,26.875 62.125,26.75 62.125,21.75 61.5,21.125 v1(60.875,21.125)
  Bottom Layer w0.125: v1(50.375,66.525) 51.25,66.525 53.05,64.725 55.125,64.725 56.5,66.1 J21.5@56.5,66.8
DISP0_DAT4: J21.6 U1.AA9 | length 53.9
  Top Layer w0.125: U1.AA9@63.5,22.5 v1(64.125,23.125)
  Layer 5 w0.125: v1(57.2,68.25) 57.2,67.075 55.937,65.812 55.937,59.229 56.492,58.675 59.096,58.675 61.487,56.284 61.487,51.611 62.406,50.692 62.433,50.692 62.987,50.138 62.987,31.072 65,29.06 65,26.25 63.875,25.125 63.875,23.375 v1(64.125,23.125)
  Bottom Layer w0.125: J21.6@57,66.8 57,68.05 v1(57.2,68.25)
DISP0_DAT5: J21.7 U1.AD7 | length 65.4
  Top Layer w0.125: U1.AD7@59.5,16.5 v1(60.5,16.625)
  Layer 5 w0.125: v1(50.6,65.725) 51.325,65 51.325,63.925 52.15,63.1 52.15,59.685 54.422,57.413 54.678,57.413 58.075,54.015 58.075,50.732 60.25,48.557 60.25,45.875 60.25,45.829 60.663,45.417 60.663,43.872 60.25,43.46 60.25,30.667 62.5,28.417 62.5,26.75 62.375,26.625 62.375,19.875 60.25,17.75 60.25,16.875 v1(60.5,16.625)
  Bottom Layer w0.125: v1(50.6,65.725) 51.475,65.725 52.725,64.475 52.968,64.475 55.925,64.475 57.5,66.05 J21.7@57.5,66.8
DISP0_DAT6: J21.8 U1.AB7 | length 59.2
  Top Layer w0.125: U1.AB7@59.5,20.5 60.125,21.125 60.75,21.75 v1(61,21.75)
  Layer 5 w0.125: v1(50.525,63.775) 51.65,62.65 51.65,59.477 54.215,56.913 54.471,56.913 57.575,53.808 57.575,50.525 59.75,48.35 59.75,46.082 59.75,45.622 60.163,45.21 60.163,44.079 59.75,43.667 59.75,30.46 62,28.21 62,26.979 61.875,26.854 61.875,26.646 61.875,22.625 v1(61,21.75)
  Bottom Layer w0.125: v1(50.525,63.775) 50.775,63.525 52.3,63.525 53,64.225 53.071,64.225 56.325,64.225 58,65.9 J21.8@58,66.8
DISP0_DAT7: J21.9 U1.AC7 | length 60.9
  Top Layer w0.125: v1(56.5,20.5) 57.875,19.125 58.875,19.125 U1.AC7@59.5,18.5
  Layer 3 w0.125: v1(53.25,67.25) 53.25,64.275 52.713,63.738 52.713,52.287 53.837,51.163 53.837,49.159 55,47.996 55,45.261 54.413,44.673 54.413,27.641 55.2,26.854 55.2,21.8 v1(56.5,20.5)
  Bottom Layer w0.125: v1@53.125,67.4 53.05,67.475 53.05,68.175 53.6,68.725 57.825,68.725 58.5,68.05 J21.9@58.5,66.8
DISP0_DAT8: J21.10 U1.AA8 | length 57.4
  Top Layer w0.125: v1(60.875,23.125) U1.AA8@61.5,22.5
  Layer 5 w0.125: v1(50.5,63.125) 51.4,62.225 51.4,59.357 53.887,56.87 53.887,56.329 55.712,54.504 55.712,51.092 57.25,49.555 57.25,44.55 58.763,43.037 58.763,39.721 58.337,39.296 58.337,38.329 58.579,38.087 58.587,38.087 59.375,37.3 59.375,30.481 61.75,28.106 61.75,27.082 61.625,26.957 61.625,26.543 61.625,23.875 v1(60.875,23.125)
  Bottom Layer w0.125: v1(50.5,63.125) 52.325,63.125 53.175,63.975 58.111,63.975 59,64.864 59,65.875 J21.10@59,66.8
DISP0_DAT9: J21.11 U1.AB6 | length 54.6
  Top Layer w0.125: v1(56.875,21.125) U1.AB6@57.5,20.5
  Layer 3 w0.125: v1(53.225,63.4) 53.85,62.775 53.85,61.25 52.963,60.363 52.963,52.412 54.087,51.288 54.087,49.263 55.25,48.1 55.25,45.157 54.663,44.57 54.663,27.745 55.5,26.907 55.5,22.5 v1(56.875,21.125)
  Bottom Layer w0.125: v1(53.225,63.4) 53.55,63.725 58.214,63.725 59.5,65.011 J21.11@59.5,66.8
DISP0_DAT10: J21.12 U1.Y8 | length 61.9
  Top Layer w0.125: v1(60.875,25.125) U1.Y8@61.5,24.5
  Layer 5 w0.125: v1(50.25,68.375) 49.675,67.8 49.675,62.983 50.713,61.946 50.713,61.912 50.725,61.9 50.725,60.2 49.825,59.3 49.825,58.967 50.079,58.712 50.485,58.712 51.837,57.36 51.837,56.777 54.962,53.652 54.962,50.782 56.463,49.282 56.463,44.277 58.013,42.727 58.013,40.032 57.587,39.607 57.587,38.018 58.268,37.337 58.277,37.337 58.625,36.989 58.625,30.125 59.604,29.146 59.604,27.729 59.875,27.457 59.875,27.043 59.875,26.125 v1(60.875,25.125)
  Bottom Layer w0.125: v1@50.25,68.45 50.775,68.975 58.951,68.975 60,67.926 J21.12@60,66.8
